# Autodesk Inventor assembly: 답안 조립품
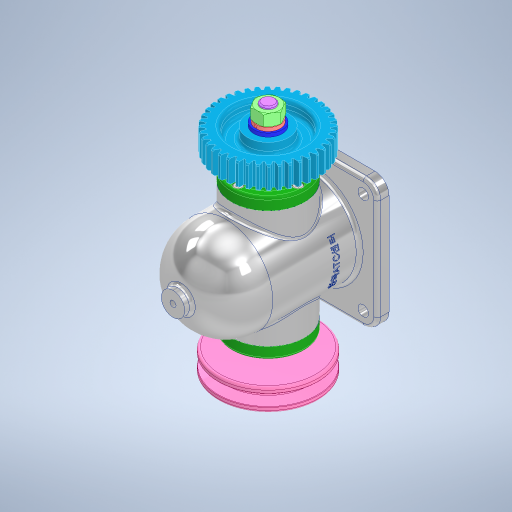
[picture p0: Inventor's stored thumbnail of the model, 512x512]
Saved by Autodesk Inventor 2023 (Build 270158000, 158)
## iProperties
Created: 2025-04
Part Number: 답안 조립품
Document SubType Name: Assembly
Designer: ADMIN_PC
Author: ADMIN_PC
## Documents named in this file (14)
- C:\Users\ADMIN_PC\Desktop\750406V1008\답안 조립품.iam
- C:\Users\ADMIN_PC\Desktop\750406V1008\본체.ipt
- C:\Users\ADMIN_PC\Desktop\750406V1008\깊은 홈 볼 베어링 6203.ipt
- C:\Users\ADMIN_PC\Desktop\750406V1008\축.ipt
- C:\Users\ADMIN_PC\Desktop\750406V1008\커버.ipt
- C:\Users\ADMIN_PC\Desktop\750406V1008\오일 실 26 38 8.ipt
- C:\Users\ADMIN_PC\Desktop\750406V1008\6각 구멍붙이 볼트 M4x12.ipt
- C:\Users\ADMIN_PC\Desktop\750406V1008\칼라.ipt
- C:\Users\ADMIN_PC\Desktop\750406V1008\평행 키 5x5x12.ipt
- C:\Users\ADMIN_PC\Desktop\750406V1008\스퍼기어.ipt
- C:\Users\ADMIN_PC\Desktop\750406V1008\V 벨트 풀리.ipt
- C:\Users\ADMIN_PC\Desktop\750406V1008\평와셔 M12.ipt
- C:\Users\ADMIN_PC\Desktop\750406V1008\스프링 와셔 M12.ipt
- C:\Users\ADMIN_PC\Desktop\750406V1008\6각 너트 M12x1.ipt
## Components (11 placed, 3 different names)
1. 6각 구멍붙이 볼트 M4x12:1
2. 6각 구멍붙이 볼트 M4x12:2
3. 6각 구멍붙이 볼트 M4x12:3
4. 6각 구멍붙이 볼트 M4x12:4
5. 6각 구멍붙이 볼트 M4x12:5
6. 6각 구멍붙이 볼트 M4x12:6
7. 6각 구멍붙이 볼트 M4x12:7
8. 6각 구멍붙이 볼트 M4x12:8
9. V 벨트 풀리:1
10. 6각 너트 M12x1:1
11. 6각 너트 M12x1:2
